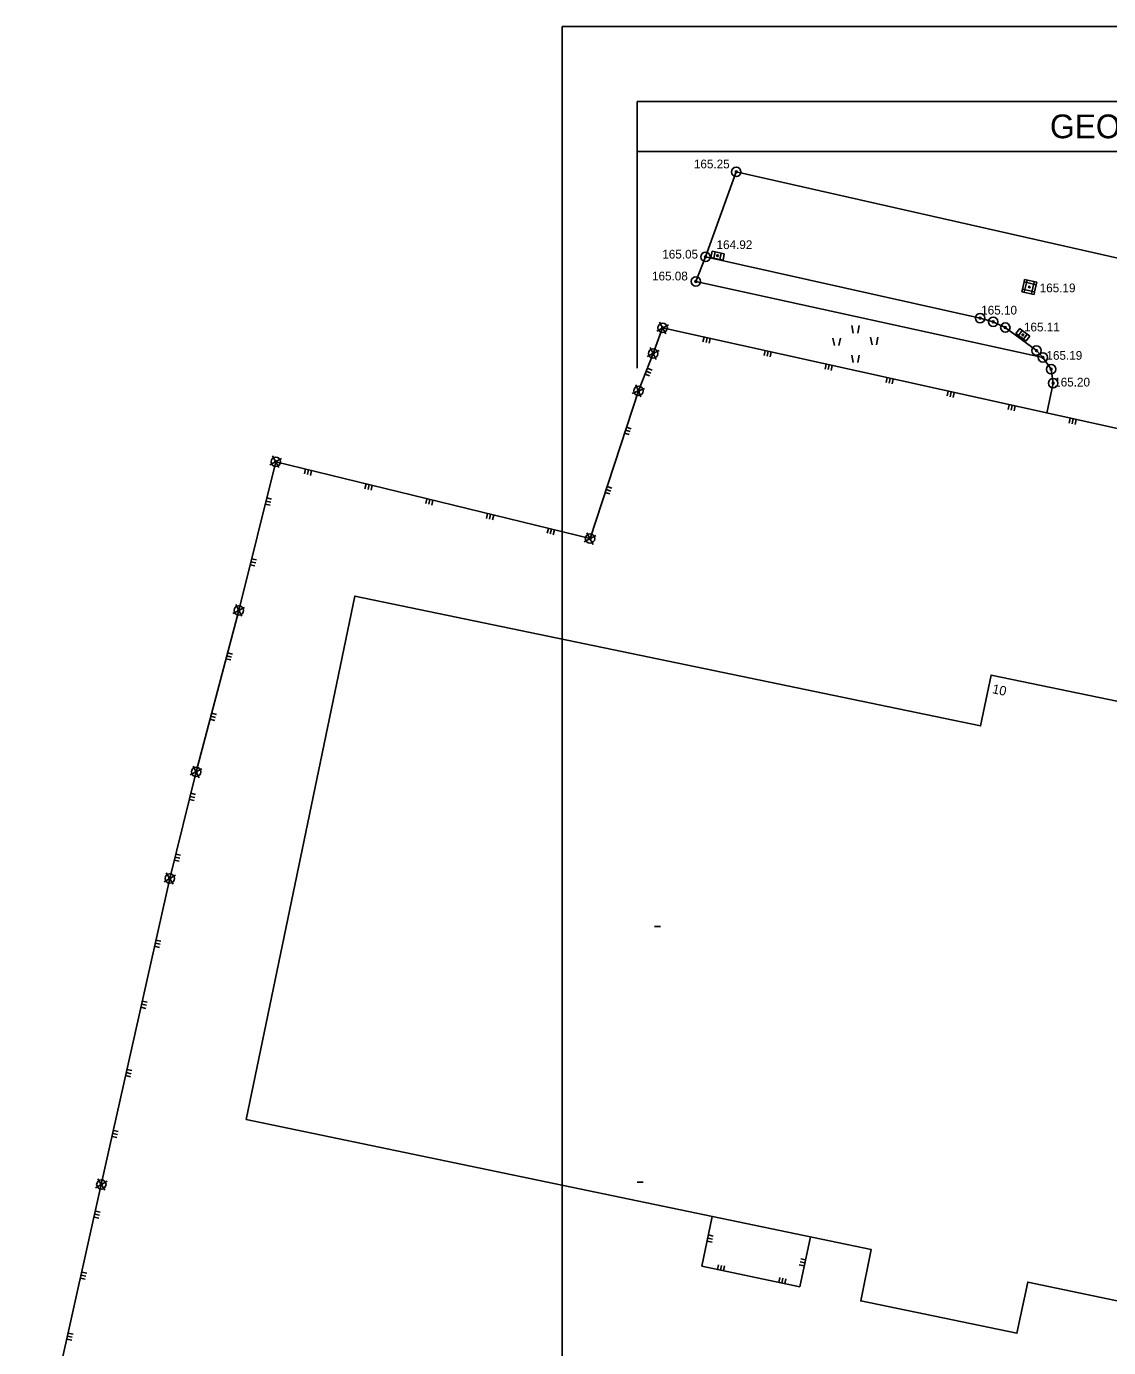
# Model space of a CAD drawing. Extents: x 492698 to 492905, y 5129124 to 5129334.
# Drawn here: x 492706.1 to 492792.6, y 5129228 to 5129333.7 of the extents above; entities that cross this region are included whole.
import ezdxf

# ---------------------------------------------------------------- set-up
doc = ezdxf.new("R2010")
doc.units = 0
for name, color, linetype in [('FRONTOVI', 7, 'Continuous'), ('KUĆNI BROJ', 7, 'Continuous'), ('MEĐA - stara', 7, 'Continuous'), ('MEĐAŠI', 7, 'Continuous'), ('OBJEKTI - stari', 7, 'Continuous'), ('OBRAZCI', 7, 'Continuous'), ('TOPO - Znakovi', 7, 'Continuous'), ('VISINE', 7, 'Continuous')]:
    doc.layers.add(name, color=color, linetype=linetype)

msp = doc.modelspace()

# ---------------------------------------------------------------- linework, layer by layer
at = {"layer": 'FRONTOVI'}
for p, q in [((492757.43, 5129309.83), (492756.49, 5129309.33)), ((492756.71, 5129310.05), (492757.21, 5129309.11)), ((492756.67, 5129307.78), (492755.73, 5129307.28)), ((492755.95, 5129308), (492756.45, 5129307.06)), ((492755.51, 5129304.74), (492754.53, 5129304.34)), ((492754.82, 5129305.03), (492755.22, 5129304.05)), ((492725.55, 5129298.61), (492726.47, 5129299.13)), ((492725.75, 5129299.33), (492726.27, 5129298.41)), ((492751.62, 5129292.97), (492750.68, 5129292.47)), ((492750.9, 5129293.19), (492751.4, 5129292.25)), ((492723.52, 5129287.21), (492722.58, 5129286.73)), ((492722.81, 5129287.44), (492723.29, 5129286.5)), ((492719.4, 5129274.51), (492719.88, 5129273.57)), ((492720.11, 5129274.28), (492719.17, 5129273.8)), ((492717.98, 5129265.79), (492717.08, 5129265.25)), ((492717.26, 5129265.97), (492717.8, 5129265.07)), ((492712.52, 5129241.29), (492711.6, 5129240.75)), ((492711.79, 5129241.48), (492712.33, 5129240.56))]:
    msp.add_line(p, q, dxfattribs=at)
for centre in [(492756.96, 5129309.58), (492756.2, 5129307.53), (492755.02, 5129304.54), (492726.01, 5129298.87), (492751.15, 5129292.72), (492723.05, 5129286.97), (492719.64, 5129274.04), (492717.53, 5129265.52), (492712.06, 5129241.02)]:
    msp.add_circle(centre, 0.075, dxfattribs=at)
for centre, start, end in [((492756.96, 5129309.58), 162.5446, 342.5446), ((492756.96, 5129309.58), 342.5446, 162.5446), ((492756.2, 5129307.53), 162.5446, 342.5446), ((492756.2, 5129307.53), 342.5446, 162.5446), ((492755.02, 5129304.54), 156.851, 336.851), ((492755.02, 5129304.54), 336.851, 156.851), ((492726.01, 5129298.87), 73.7731, 253.7731), ((492726.01, 5129298.87), 253.7731, 73.7731), ((492751.15, 5129292.72), 162.7497, 342.7497), ((492751.15, 5129292.72), 342.7497, 162.7497), ((492723.05, 5129286.97), 161.5894, 341.5894), ((492723.05, 5129286.97), 341.5894, 161.5894), ((492719.64, 5129274.04), 161.8815, 341.8815), ((492719.64, 5129274.04), 341.8815, 161.8815), ((492717.53, 5129265.52), 346.069, 166.069), ((492717.53, 5129265.52), 166.069, 346.069), ((492712.06, 5129241.02), 165.0577, 345.0577), ((492712.06, 5129241.02), 345.0577, 165.0577)]:
    msp.add_arc(centre, 0.075, start, end, dxfattribs=at)
at = {"layer": 'MEĐA - stara'}
for p, q in [((492760.39, 5129315.26), (492762.85, 5129322.07)), ((492762.85, 5129322.07), (492807.48, 5129311.96)), ((492759.62, 5129313.3), (492760.39, 5129315.26)), ((492760.39, 5129315.26), (492782.35, 5129310.37)), ((492787.38, 5129307.22), (492759.62, 5129313.3)), ((492756.96, 5129309.58), (492756.2, 5129307.53)), ((492817.66, 5129296.12), (492756.96, 5129309.58)), ((492772.08, 5129309.76), (492772.21, 5129309.16)), ((492772.68, 5129309.76), (492772.56, 5129309.16)), ((492782.35, 5129310.37), (492783.4, 5129310.07)), ((492783.4, 5129310.07), (492784.37, 5129309.61)), ((492784.37, 5129309.61), (492786.86, 5129307.76)), ((492770.58, 5129308.76), (492770.71, 5129308.16)), ((492771.18, 5129308.76), (492771.06, 5129308.16)), ((492773.58, 5129308.83), (492773.71, 5129308.23)), ((492774.18, 5129308.83), (492774.06, 5129308.23)), ((492756.2, 5129307.53), (492755.02, 5129304.54)), ((492772.08, 5129307.41), (492772.21, 5129306.81)), ((492772.68, 5129307.41), (492772.56, 5129306.81)), ((492786.86, 5129307.76), (492787.38, 5129307.22)), ((492788.03, 5129306.27), (492787.38, 5129307.22)), ((492788.19, 5129305.15), (492788.03, 5129306.27)), ((492787.7, 5129302.76), (492788.19, 5129305.15)), ((492755.02, 5129304.54), (492751.15, 5129292.72)), ((492726.01, 5129298.87), (492723.05, 5129286.97)), ((492751.15, 5129292.72), (492726.01, 5129298.87)), ((492723.05, 5129286.97), (492719.64, 5129274.04)), ((492719.64, 5129274.04), (492717.53, 5129265.52)), ((492717.53, 5129265.52), (492712.06, 5129241.02)), ((492712.06, 5129241.02), (492706.07, 5129214.16))]:
    msp.add_line(p, q, dxfattribs=at)
at = {"layer": 'MEĐAŠI'}
for centre, radius in [((492762.85, 5129322.07), 0.375), ((492762.85, 5129322.07), 0.075), ((492760.39, 5129315.26), 0.375), ((492760.39, 5129315.26), 0.075), ((492759.62, 5129313.3), 0.375), ((492759.62, 5129313.3), 0.075), ((492782.35, 5129310.37), 0.375), ((492782.35, 5129310.37), 0.075), ((492783.4, 5129310.07), 0.375), ((492756.96, 5129309.58), 0.375), ((492783.4, 5129310.07), 0.075), ((492784.37, 5129309.61), 0.375), ((492784.37, 5129309.61), 0.075), ((492756.2, 5129307.53), 0.375), ((492786.86, 5129307.76), 0.375), ((492786.86, 5129307.76), 0.075), ((492787.38, 5129307.22), 0.375), ((492787.38, 5129307.22), 0.075), ((492788.03, 5129306.27), 0.375), ((492788.03, 5129306.27), 0.075), ((492788.19, 5129305.15), 0.375), ((492788.19, 5129305.15), 0.075), ((492755.02, 5129304.54), 0.375), ((492726.01, 5129298.87), 0.375), ((492751.15, 5129292.72), 0.375), ((492723.05, 5129286.97), 0.375), ((492719.64, 5129274.04), 0.375), ((492717.53, 5129265.52), 0.375), ((492712.06, 5129241.02), 0.375)]:
    msp.add_circle(centre, radius, dxfattribs=at)
at = {"layer": 'OBJEKTI - stari'}
for p, q in [((492760.09, 5129234.48), (492760.93, 5129238.46)), ((492768.78, 5129236.83), (492767.93, 5129232.82)), ((492767.93, 5129232.82), (492760.09, 5129234.48))]:
    msp.add_line(p, q, dxfattribs=at)
msp.add_lwpolyline([(492805.42, 5129272.95), (492801.38, 5129253.83), (492798.48, 5129239.95), (492796.63, 5129231.02), (492786.16, 5129233.21), (492785.3, 5129229.11), (492772.8, 5129231.7), (492773.65, 5129235.81), (492723.64, 5129246.23), (492732.34, 5129288.11), (492782.39, 5129277.73), (492783.23, 5129281.79), (492795.74, 5129279.2), (492794.89, 5129275.14)], close=True, dxfattribs=at)
at = {"layer": 'OBRAZCI'}
for p, q in [((492748.91, 5129333.71), (492748.91, 5129123.71)), ((492748.91, 5129333.71), (492897.41, 5129333.71)), ((492754.91, 5129327.71), (492891.41, 5129327.71)), ((492754.91, 5129327.71), (492754.91, 5129306.37)), ((492754.91, 5129327.71), (492847.91, 5129327.71)), ((492754.91, 5129327.71), (492847.91, 5129327.71)), ((492754.91, 5129327.71), (492847.91, 5129327.71)), ((492754.91, 5129327.71), (492847.91, 5129327.71)), ((492754.91, 5129323.71), (492891.41, 5129323.71)), ((492756.3, 5129261.68), (492756.8, 5129261.68)), ((492754.91, 5129241.21), (492755.41, 5129241.21))]:
    msp.add_line(p, q, dxfattribs=at)
at = {"layer": 'TOPO - Znakovi'}
for p, q in [((492760.91, 5129315.71), (492760.81, 5129315.22)), ((492761.16, 5129315.66), (492760.91, 5129315.71)), ((492760.81, 5129315.22), (492761.05, 5129315.17)), ((492761.16, 5129315.66), (492761.05, 5129315.17)), ((492761.05, 5129315.17), (492761.54, 5129315.06)), ((492761.65, 5129315.55), (492761.16, 5129315.66)), ((492761.65, 5129315.55), (492761.54, 5129315.06)), ((492761.54, 5129315.06), (492761.79, 5129315.01)), ((492761.89, 5129315.5), (492761.65, 5129315.55)), ((492761.79, 5129315.01), (492761.89, 5129315.5)), ((492785.74, 5129312.68), (492785.69, 5129312.48)), ((492785.87, 5129313.26), (492785.74, 5129312.68)), ((492786.71, 5129312.46), (492785.74, 5129312.68)), ((492785.91, 5129313.46), (492785.87, 5129313.26)), ((492786.84, 5129313.04), (492785.87, 5129313.26)), ((492786.11, 5129313.41), (492785.89, 5129312.44)), ((492786.89, 5129313.24), (492785.91, 5129313.46)), ((492786.47, 5129312.31), (492786.69, 5129313.28)), ((492786.71, 5129312.46), (492786.84, 5129313.04)), ((492786.84, 5129313.04), (492786.89, 5129313.24)), ((492785.69, 5129312.48), (492786.67, 5129312.26)), ((492786.67, 5129312.26), (492786.71, 5129312.46)), ((492785.52, 5129309.52), (492785.22, 5129309.12)), ((492785.72, 5129309.37), (492785.42, 5129308.97)), ((492785.72, 5129309.37), (492785.52, 5129309.52)), ((492786.12, 5129309.07), (492785.72, 5129309.37)), ((492760.18, 5129308.46), (492760.27, 5129308.85)), ((492760.43, 5129308.4), (492760.51, 5129308.79)), ((492760.67, 5129308.35), (492760.76, 5129308.74)), ((492785.22, 5129309.12), (492785.42, 5129308.97)), ((492785.42, 5129308.97), (492785.82, 5129308.67)), ((492786.12, 5129309.07), (492785.82, 5129308.67)), ((492785.82, 5129308.67), (492786.02, 5129308.52)), ((492786.02, 5129308.52), (492786.32, 5129308.92)), ((492786.32, 5129308.92), (492786.12, 5129309.07)), ((492765.07, 5129307.37), (492765.15, 5129307.76)), ((492765.31, 5129307.32), (492765.4, 5129307.71)), ((492765.55, 5129307.26), (492765.64, 5129307.66)), ((492756.11, 5129306.2), (492755.73, 5129306.35)), ((492769.95, 5129306.29), (492770.03, 5129306.68)), ((492770.19, 5129306.24), (492770.28, 5129306.63)), ((492770.44, 5129306.18), (492770.52, 5129306.57)), ((492755.92, 5129305.74), (492755.55, 5129305.88)), ((492756.01, 5129305.97), (492755.64, 5129306.12)), ((492774.83, 5129305.21), (492774.92, 5129305.6)), ((492775.07, 5129305.15), (492775.16, 5129305.54)), ((492775.32, 5129305.1), (492775.4, 5129305.49)), ((492779.71, 5129304.13), (492779.8, 5129304.52)), ((492779.95, 5129304.07), (492780.04, 5129304.46)), ((492780.2, 5129304.02), (492780.28, 5129304.41)), ((492784.59, 5129303.04), (492784.68, 5129303.43)), ((492784.84, 5129302.99), (492784.92, 5129303.38)), ((492785.08, 5129302.93), (492785.17, 5129303.33)), ((492789.47, 5129301.96), (492789.56, 5129302.35)), ((492789.72, 5129301.91), (492789.8, 5129302.3)), ((492789.96, 5129301.85), (492790.05, 5129302.24)), ((492754.29, 5129301.04), (492753.91, 5129301.16)), ((492754.37, 5129301.28), (492753.99, 5129301.4)), ((492754.45, 5129301.51), (492754.07, 5129301.64)), ((492728.3, 5129297.9), (492728.39, 5129298.29)), ((492728.54, 5129297.84), (492728.63, 5129298.23)), ((492728.78, 5129297.78), (492728.88, 5129298.17)), ((492733.15, 5129296.71), (492733.25, 5129297.1)), ((492733.4, 5129296.65), (492733.49, 5129297.04)), ((492733.64, 5129296.59), (492733.73, 5129296.98)), ((492752.89, 5129296.76), (492752.51, 5129296.89)), ((492725.62, 5129295.63), (492725.23, 5129295.72)), ((492725.68, 5129295.87), (492725.29, 5129295.97)), ((492738.01, 5129295.52), (492738.1, 5129295.91)), ((492738.25, 5129295.46), (492738.35, 5129295.85)), ((492738.5, 5129295.4), (492738.59, 5129295.79)), ((492752.74, 5129296.29), (492752.36, 5129296.41)), ((492752.82, 5129296.52), (492752.44, 5129296.65)), ((492725.56, 5129295.39), (492725.17, 5129295.48)), ((492742.87, 5129294.33), (492742.96, 5129294.72)), ((492743.11, 5129294.28), (492743.2, 5129294.66)), ((492743.35, 5129294.22), (492743.45, 5129294.6)), ((492747.72, 5129293.15), (492747.82, 5129293.53)), ((492747.97, 5129293.09), (492748.06, 5129293.48)), ((492748.21, 5129293.03), (492748.3, 5129293.42)), ((492724.35, 5129290.53), (492723.96, 5129290.63)), ((492724.41, 5129290.78), (492724.02, 5129290.87)), ((492724.47, 5129291.02), (492724.08, 5129291.11)), ((492722.42, 5129283), (492722.03, 5129283.1)), ((492722.48, 5129283.24), (492722.09, 5129283.34)), ((492722.54, 5129283.48), (492722.16, 5129283.58)), ((492721.27, 5129278.65), (492720.88, 5129278.75)), ((492721.14, 5129278.16), (492720.75, 5129278.26)), ((492721.2, 5129278.4), (492720.82, 5129278.51)), ((492719.48, 5129271.75), (492719.1, 5129271.84)), ((492719.54, 5129271.99), (492719.16, 5129272.08)), ((492719.6, 5129272.23), (492719.22, 5129272.33)), ((492718.34, 5129267.13), (492717.95, 5129267.23)), ((492718.4, 5129267.38), (492718.01, 5129267.47)), ((492718.28, 5129266.89), (492717.89, 5129266.99)), ((492716.71, 5129260), (492716.32, 5129260.09)), ((492716.76, 5129260.25), (492716.37, 5129260.33)), ((492716.82, 5129260.49), (492716.43, 5129260.58)), ((492715.67, 5129255.37), (492715.28, 5129255.45)), ((492715.73, 5129255.61), (492715.34, 5129255.7)), ((492715.62, 5129255.12), (492715.23, 5129255.21)), ((492714.51, 5129250.14), (492714.11, 5129250.22)), ((492714.4, 5129249.65), (492714.01, 5129249.74)), ((492714.45, 5129249.89), (492714.06, 5129249.98)), ((492713.31, 5129244.77), (492712.92, 5129244.86)), ((492713.36, 5129245.01), (492712.97, 5129245.1)), ((492713.42, 5129245.26), (492713.03, 5129245.34)), ((492711.92, 5129238.56), (492711.53, 5129238.65)), ((492711.98, 5129238.8), (492711.59, 5129238.89)), ((492711.87, 5129238.32), (492711.48, 5129238.4)), ((492760.91, 5129236.41), (492760.52, 5129236.49)), ((492760.96, 5129236.65), (492760.57, 5129236.73)), ((492761.01, 5129236.89), (492760.62, 5129236.98)), ((492761.43, 5129234.6), (492761.35, 5129234.21)), ((492761.68, 5129234.55), (492761.59, 5129234.16)), ((492761.92, 5129234.5), (492761.84, 5129234.11)), ((492767.89, 5129234.58), (492768.29, 5129234.5)), ((492767.95, 5129234.83), (492768.34, 5129234.75)), ((492768, 5129235.07), (492768.39, 5129234.99)), ((492710.78, 5129233.44), (492710.39, 5129233.52)), ((492710.83, 5129233.68), (492710.44, 5129233.77)), ((492710.89, 5129233.92), (492710.5, 5129234.01)), ((492766.32, 5129233.57), (492766.24, 5129233.18)), ((492766.57, 5129233.52), (492766.49, 5129233.13)), ((492766.81, 5129233.47), (492766.73, 5129233.07)), ((492709.8, 5129229.04), (492709.41, 5129229.13)), ((492709.69, 5129228.56), (492709.3, 5129228.64)), ((492709.74, 5129228.8), (492709.35, 5129228.89))]:
    msp.add_line(p, q, dxfattribs=at)
for centre in [(492761.35, 5129315.36), (492786.29, 5129312.86), (492785.77, 5129309.02)]:
    msp.add_circle(centre, 0.065, dxfattribs=at)

# ---------------------------------------------------------------- texts
at = {"layer": 'KUĆNI BROJ'}
msp.add_text('10', height=0.75, rotation=348.3031, dxfattribs=at).set_placement((492783.28, 5129280.35))
at = {"layer": 'OBRAZCI'}
msp.add_text('GEODETSKI SITUACIJSKI NACRT STVARNOG STANJA', height=1.9, dxfattribs=at).set_placement((492787.94, 5129324.76))
at = {"layer": 'VISINE'}
for s, p in [('165.25', (492759.46, 5129322.35)), ('165.05', (492756.93, 5129315.13)), ('164.92', (492761.27, 5129315.89)), ('165.08', (492756.11, 5129313.38)), ('165.19', (492787.12, 5129312.43)), ('165.10', (492782.44, 5129310.65)), ('165.11', (492785.86, 5129309.3)), ('165.19', (492787.66, 5129307.03)), ('165.20', (492788.28, 5129304.89))]:
    msp.add_text(s, height=0.7, dxfattribs=at).set_placement(p)

doc.saveas('drawing.dxf')
